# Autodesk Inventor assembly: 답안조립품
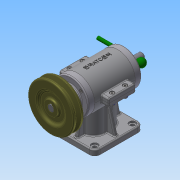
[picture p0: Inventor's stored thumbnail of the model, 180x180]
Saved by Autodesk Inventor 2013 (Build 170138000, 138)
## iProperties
Created: 2015-12
Part Number: 답안조립품
Document SubType Name: Assembly
Designer: Administrator
Author: Administrator
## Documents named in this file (19)
- C:\Users\Administrator\Desktop\351208V1039\답안조립품.iam
- C:\Users\Administrator\Desktop\351208V1039\본체.ipt
- C:\Users\Administrator\Desktop\351208V1039\V-벨트풀리.ipt
- C:\Users\Administrator\Desktop\351208V1039\너트 M4.ipt
- C:\Users\Administrator\Desktop\351208V1039\뒤커버.ipt
- C:\Users\Administrator\Desktop\351208V1039\레바.ipt
- C:\Users\Administrator\Desktop\351208V1039\멈춤나사 M3x8.ipt
- C:\Users\Administrator\Desktop\351208V1039\베어링 6201.ipt
- C:\Users\Administrator\Desktop\351208V1039\베어링 6202.ipt
- C:\Users\Administrator\Desktop\351208V1039\본체커버.ipt
- C:\Users\Administrator\Desktop\351208V1039\볼트 M3x0.5x8.ipt
- C:\Users\Administrator\Desktop\351208V1039\볼트 M4 x 16.ipt
- C:\Users\Administrator\Desktop\351208V1039\슬라이드.ipt
- C:\Users\Administrator\Desktop\351208V1039\앞커버.ipt
- C:\Users\Administrator\Desktop\351208V1039\오일실 12 22 7.ipt
- C:\Users\Administrator\Desktop\351208V1039\와셔 ST 4-100.ipt
- C:\Users\Administrator\Desktop\351208V1039\키 4 x 4 x 18.ipt
- C:\Users\Administrator\Desktop\351208V1039\편심축.ipt
- C:\Users\Administrator\Desktop\351208V1039\스프링1.ipt
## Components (13 placed, 4 different names)
1. V-벨트풀리:1 — 플러쉬:1
2. ISO 4032 M4:1
3. ISO 4762 M4 x 16:1
4. ISO 7091 ST 4 - 100 HV:1
5. ISO 4762 M4 x 16:2
6. ISO 4762 M4 x 16:3
7. ISO 4762 M4 x 16:4
8. ISO 4032 M4:2
9. ISO 4032 M4:3
10. ISO 4032 M4:4
11. ISO 7091 ST 4 - 100 HV:2
12. ISO 7091 ST 4 - 100 HV:3
13. ISO 7091 ST 4 - 100 HV:4
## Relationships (1: Flush 1)
- 플러쉬:1 [Flush]: V-벨트풀리:1
